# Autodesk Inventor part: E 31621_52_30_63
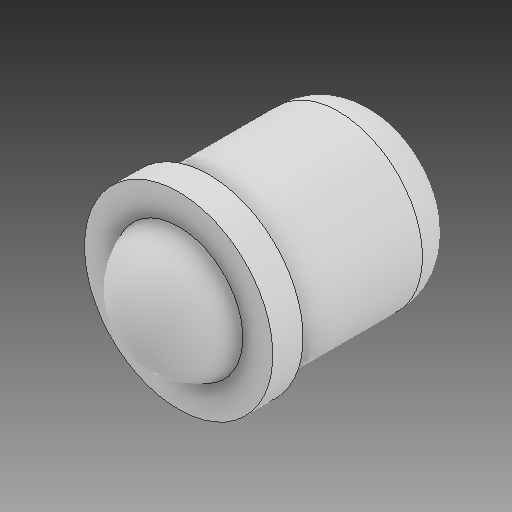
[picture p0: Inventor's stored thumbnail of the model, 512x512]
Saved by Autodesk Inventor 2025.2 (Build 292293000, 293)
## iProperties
Created: 2025-03
Part Number: E 31621_52_30_63
Material: Všeobecné
Document SubType Name: Modeling
Designer: Patrik
Density: 1 g/cm^3
Appearance: Výchozí
Description: Pojezd
Stock Number: Pojezd
Mass: 0.127068 g
Surface Area: 1.42239 cm^2
Volume: 0.127068 cm^3
Author: Patrik
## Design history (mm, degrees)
feature "Base1"
node "Těleso1"
